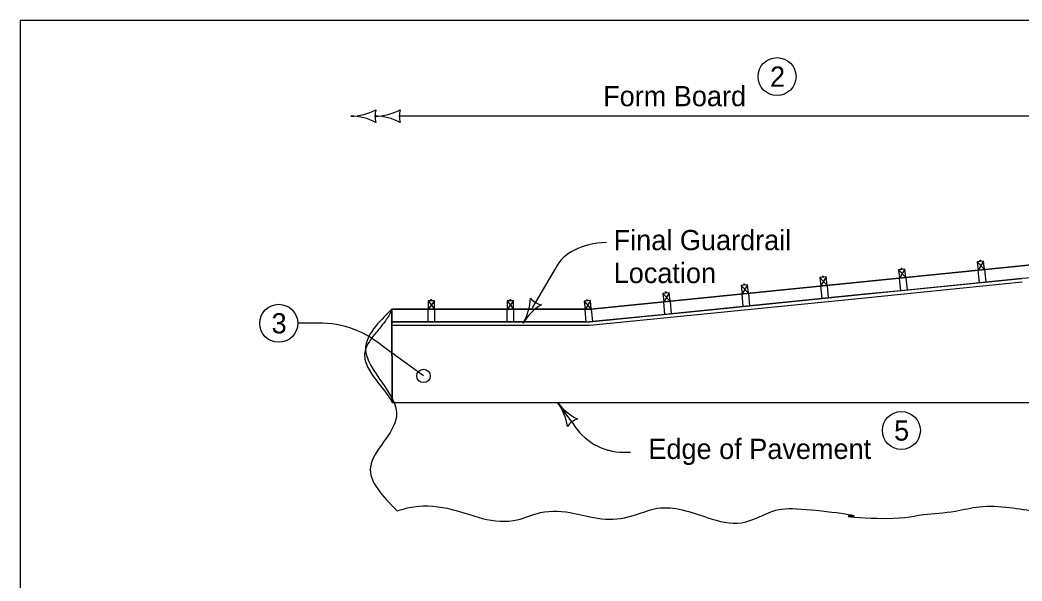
# Model space of a CAD drawing. Extents: x -1548 to 1548, y -960 to 993.
# Drawn here: x -1548 to -756, y 206 to 650 of the extents above; entities that cross this region are included whole.
import ezdxf

# ---------------------------------------------------------------- set-up
doc = ezdxf.new("R2010")
doc.units = 0
for name, color, linetype in [('dsnCellElements', 7, 'Continuous'), ('dsnStdBorder', 7, 'Continuous'), ('dsnStdDimension', 7, 'Continuous'), ('dsnStdLabel', 7, 'Continuous'), ('dsnStdLineWork', 7, 'Continuous'), ('dsnStdNote', 7, 'Continuous'), ('Level 4', 7, 'Continuous')]:
    doc.layers.add(name, color=color, linetype=linetype)

msp = doc.modelspace()

# ---------------------------------------------------------------- linework, layer by layer
at = {"layer": 'dsnCellElements'}
for p, q in [((-786.44, 459.3), (-790.75, 452.16)), ((-789.02, 460.01), (-789.03, 460.08)), ((-853.6, 452.55), (-847.96, 446.41)), ((-848.63, 453.05), (-852.93, 445.91)), ((-851.21, 453.76), (-851.22, 453.83)), ((-791.41, 458.8), (-785.77, 452.66)), ((-790.75, 452.16), (-785.77, 452.66)), ((-789.75, 442.2), (-790.75, 452.16)), ((-785.77, 452.66), (-784.77, 442.71)), ((-915.79, 446.3), (-910.15, 440.16)), ((-910.81, 446.8), (-915.12, 439.66)), ((-913.4, 447.51), (-913.4, 447.58)), ((-880.54, 433.08), (-756.17, 445.58)), ((-852.93, 445.91), (-847.96, 446.41)), ((-851.93, 435.95), (-852.93, 445.91)), ((-847.96, 446.41), (-846.95, 436.46)), ((-727.23, 447.86), (-756.17, 445.58)), ((-977.97, 440.05), (-972.33, 433.91)), ((-973, 440.55), (-977.31, 433.41)), ((-975.58, 441.26), (-975.59, 441.33)), ((-915.12, 439.66), (-910.14, 440.16)), ((-914.12, 429.7), (-915.12, 439.66)), ((-910.14, 440.16), (-909.14, 430.21)), ((-851.93, 435.95), (-880.54, 433.08)), ((-880.27, 430.39), (-755.9, 442.89)), ((-880.27, 430.39), (-755.9, 442.89)), ((-846.95, 436.46), (-851.93, 435.95)), ((-846.95, 436.46), (-851.93, 435.95)), ((-784.77, 442.71), (-789.75, 442.2)), ((-1225.42, 427.94), (-1220.42, 421.27)), ((-1220.42, 427.94), (-1225.42, 421.27)), ((-1222.92, 428.91), (-1222.92, 428.98)), ((-1162.92, 427.94), (-1157.92, 421.27)), ((-1157.92, 427.94), (-1162.92, 421.27)), ((-1160.42, 428.91), (-1160.42, 428.98)), ((-1102.07, 427.58), (-1096.43, 421.44)), ((-1097.09, 428.07), (-1101.41, 420.94)), ((-1099.68, 428.79), (-1099.68, 428.86)), ((-1039.88, 433.79), (-1034.24, 427.66)), ((-1034.9, 434.29), (-1039.22, 427.16)), ((-1039.22, 427.16), (-1034.24, 427.66)), ((-1037.49, 435.01), (-1037.5, 435.08)), ((-1034.24, 427.66), (-1033.24, 417.7)), ((-1004.91, 420.58), (-880.54, 433.08)), ((-1004.64, 417.89), (-880.27, 430.39)), ((-1004.64, 417.89), (-880.27, 430.39)), ((-977.31, 433.41), (-972.33, 433.91)), ((-976.31, 423.45), (-977.31, 433.41)), ((-972.33, 433.91), (-971.33, 423.96)), ((-914.12, 429.7), (-971.33, 423.96)), ((-909.14, 430.21), (-914.12, 429.7)), ((-909.14, 430.21), (-914.12, 429.7)), ((-880.54, 433.08), (-909.14, 430.21)), ((-1225.42, 421.27), (-1220.42, 421.27)), ((-1225.42, 411.26), (-1225.42, 421.27)), ((-1220.42, 421.27), (-1220.42, 411.26)), ((-1162.92, 421.27), (-1157.92, 421.27)), ((-1162.92, 411.26), (-1162.92, 421.27)), ((-1157.92, 421.27), (-1157.92, 411.26)), ((-1101.41, 420.94), (-1096.43, 421.44)), ((-1100.41, 410.98), (-1101.41, 420.94)), ((-1097.76, 411.25), (-1004.91, 420.58)), ((-1096.43, 421.44), (-1095.43, 411.48)), ((-1038.22, 417.2), (-1039.22, 427.16)), ((-1004.91, 420.58), (-1033.24, 417.73)), ((-976.31, 423.45), (-1004.91, 420.58)), ((-971.33, 423.96), (-976.31, 423.45)), ((-971.33, 423.96), (-976.31, 423.45)), ((-1097.49, 408.55), (-1004.64, 417.89)), ((-1097.49, 408.55), (-1004.64, 417.89)), ((-1038.22, 417.23), (-1095.43, 411.48)), ((-1033.24, 417.7), (-1038.22, 417.2)), ((-1033.24, 417.7), (-1038.22, 417.2)), ((-1033.24, 417.73), (-1033.24, 417.7)), ((-1254.17, 411.26), (-1254.17, 408.55)), ((-1254.17, 411.26), (-1129.17, 411.26)), ((-1254.17, 408.55), (-1129.17, 408.55)), ((-1254.17, 408.55), (-1129.17, 408.55)), ((-1220.42, 411.26), (-1225.42, 411.26)), ((-1157.92, 411.26), (-1162.92, 411.26)), ((-1157.92, 411.26), (-1162.92, 411.26)), ((-1129.17, 411.26), (-1157.92, 411.26)), ((-1100.44, 411.26), (-1129.17, 411.26)), ((-1129.17, 411.26), (-1097.63, 411.26)), ((-1129.17, 408.55), (-1097.49, 408.55)), ((-1129.17, 408.55), (-1097.49, 408.55)), ((-1100.41, 410.98), (-1100.44, 411.26)), ((-1095.43, 411.48), (-1100.41, 410.98)), ((-1095.43, 411.48), (-1095.43, 411.48))]:
    msp.add_line(p, q, dxfattribs=at)
for points in [[(-790.75, 452.16), (-785.77, 452.66), (-786.44, 459.3), (-791.41, 458.8)], [(-852.93, 445.91), (-847.96, 446.41), (-848.63, 453.05), (-853.6, 452.55)], [(-915.12, 439.66), (-910.15, 440.16), (-910.81, 446.8), (-915.79, 446.3)], [(-977.31, 433.41), (-972.33, 433.91), (-973, 440.55), (-977.97, 440.05)], [(-1225.42, 421.27), (-1220.42, 421.27), (-1220.42, 427.94), (-1225.42, 427.94)], [(-1162.92, 421.27), (-1157.92, 421.27), (-1157.92, 427.94), (-1162.92, 427.94)], [(-1101.41, 420.94), (-1096.43, 421.44), (-1097.09, 428.07), (-1102.07, 427.58)], [(-1039.22, 427.16), (-1034.24, 427.66), (-1034.9, 434.29), (-1039.88, 433.79)]]:
    msp.add_lwpolyline(points, close=True, dxfattribs=at)
for points in [[(-789.26, 459.01), (-789.3, 459.44), (-788.64, 459.51), (-788.6, 459.08)], [(-789.16, 459.46), (-789.22, 459.99), (-788.83, 460.03), (-788.78, 459.49)], [(-851.45, 452.76), (-851.49, 453.19), (-850.82, 453.26), (-850.78, 452.83)], [(-851.35, 453.21), (-851.4, 453.74), (-851.02, 453.78), (-850.96, 453.24)], [(-913.63, 446.51), (-913.67, 446.94), (-913.01, 447.01), (-912.97, 446.58)], [(-913.54, 446.96), (-913.59, 447.49), (-913.2, 447.53), (-913.15, 446.99)], [(-756.17, 445.58), (-784.77, 442.71), (-789.75, 442.2), (-846.95, 436.46)], [(-975.82, 440.26), (-975.86, 440.69), (-975.2, 440.76), (-975.16, 440.33)], [(-975.72, 440.71), (-975.78, 441.24), (-975.39, 441.28), (-975.34, 440.74)], [(-1223.25, 427.94), (-1223.25, 428.37), (-1222.59, 428.37), (-1222.59, 427.94)], [(-1223.11, 428.37), (-1223.11, 428.91), (-1222.73, 428.91), (-1222.73, 428.37)], [(-1160.75, 427.94), (-1160.75, 428.37), (-1160.09, 428.37), (-1160.09, 427.94)], [(-1160.61, 428.37), (-1160.61, 428.91), (-1160.23, 428.91), (-1160.23, 428.37)], [(-1099.91, 427.79), (-1099.96, 428.22), (-1099.29, 428.29), (-1099.25, 427.86)], [(-1099.82, 428.23), (-1099.87, 428.77), (-1099.48, 428.81), (-1099.43, 428.27)], [(-1037.72, 434.01), (-1037.77, 434.44), (-1037.1, 434.51), (-1037.06, 434.08)], [(-1037.63, 434.45), (-1037.68, 434.99), (-1037.29, 435.03), (-1037.24, 434.49)], [(-1098.92, 421.19), (-1101.41, 420.94), (-1101.41, 420.94)], [(-1038.22, 417.2), (-1038.22, 417.23)], [(-1162.92, 411.26), (-1220.42, 411.26), (-1225.42, 411.26), (-1254.17, 411.26)], [(-1095.43, 411.48), (-1097.63, 411.26), (-1097.76, 411.25), (-1100.41, 410.98)]]:
    msp.add_lwpolyline(points, dxfattribs=at)
at = {"layer": 'dsnStdBorder'}
for q in [(-1547.84, -960), (1547.84, 650)]:
    msp.add_line((-1547.84, 650), q, dxfattribs=at)
at = {"layer": 'dsnStdDimension'}
msp.add_line((-1247.36, 574.13), (-342.58, 574.13), dxfattribs=at)
for centre, radius, start, end in [((-1286.58, 616.47), 42.5, 270, 298.07249), ((-1267.36, 616.47), 42.5, 270, 298.07249), ((-1250.95, 573.97), 16.42, 162.26665, 197.73335), ((-1231.73, 573.97), 16.42, 162.26665, 197.73335), ((-1286.58, 531.47), 42.5, 61.92751, 90), ((-1267.36, 531.47), 42.5, 61.92751, 90)]:
    msp.add_arc(centre, radius, start, end, dxfattribs=at)
at = {"layer": 'dsnStdLabel'}
for p, q in [((-1124.66, 453.64), (-1143.21, 422.3)), ((-1111.04, 331.19), (-1123.15, 347.64)), ((-1070.95, 308.12), (-1065.51, 308.12))]:
    msp.add_line(p, q, dxfattribs=at)
for centre, radius, start, end in [((-1186.97, 431.8), 42.5, 329.37973, 357.45222), ((-1132.24, 440.82), 16.42, 221.64638, 257.11308), ((-1113.82, 388.51), 42.5, 121.30724, 149.37973), ((-1088.93, 372.84), 42.5, 216.37256, 244.44505), ((-1157.37, 322.43), 42.5, 8.30007, 36.37256), ((-1102.02, 318.95), 16.42, 108.63921, 144.10591), ((-1070.9, 354.58), 46.46, 210.22743, 270)]:
    msp.add_arc(centre, radius, start, end, dxfattribs=at)
msp.add_ellipse((-1043.56, 414.6), major_axis=(-81.09, 39.04), ratio=0.555556, start_param=5.482641, end_param=6.283185, dxfattribs=at)
at = {"layer": 'dsnStdLineWork'}
for p, q in [((-1096.43, 421.27), (-732.85, 458.06)), ((-893.02, 443.91), (-893.02, 443.99)), ((-1254.17, 421.27), (-1096.43, 421.27)), ((-1253.65, 347.64), (269.95, 347.64))]:
    msp.add_line(p, q, dxfattribs=at)
msp.add_circle((-1229.05, 368.54), 5.33, dxfattribs=at)
for points in [[(-1254.17, 421.27), (-1274.82, 389.72), (-1250.46, 336.63), (-1270.92, 296.65), (-1249.88, 261.83)], [(-1249.88, 261.83), (-1240.46, 264.41), (-1210.23, 263.83), (-1182.29, 255.85), (-1154.92, 254.71), (-1136.67, 260.41), (-1109.87, 259.84), (-1085.35, 255.28), (-1061.4, 258.7), (-1044.3, 263.83), (-1004.38, 256.42), (-977.58, 252.42), (-953.06, 261.55), (-930.25, 263.26), (-891.48, 257.56), (-892.05, 257.56), (-870.89, 255.96), (-833.83, 258.81), (-808.74, 261.66), (-789.92, 265.08), (-765.97, 264.51), (-744.3, 261.09), (-718.64, 256.53), (-685, 257.67), (-653.63, 263.94), (-628.54, 263.94), (-596.61, 256.53), (-567.53, 253.67), (-533.89, 260.52), (-501.38, 263.94), (-467.17, 257.1), (-441.51, 254.24), (-419.27, 257.67), (-391.33, 273.07), (-381.07, 275.35), (-356.55, 277.63), (-325.88, 278.2), (-304.78, 278.2), (-251.47, 268.92)]]:
    msp.add_spline(points, degree=3, dxfattribs=at)
at = {"layer": 'dsnStdNote'}
for p, q in [((-1316.43, 410.15), (-1328.42, 410.15)), ((-1229.05, 368.54), (-1261.44, 392.02))]:
    msp.add_line(p, q, dxfattribs=at)
for centre in [(-949.67, 605.26), (-1343.42, 410.15), (-851.43, 325.38)]:
    msp.add_circle(centre, 15, dxfattribs=at)
msp.add_arc((-1311.25, 333.38), 76.94, 49.65511, 93.85773, dxfattribs=at)
at = {"layer": 'Level 4'}
for p, q in [((-732.85, 458.06), (-1096.43, 421.27)), ((-1096.43, 421.27), (-1254.17, 421.27)), ((-1254.17, 421.27), (-1253.71, 347.64)), ((-1253.71, 347.64), (-1254.17, 421.27)), ((-1253.71, 347.64), (-351, 347.64))]:
    msp.add_line(p, q, dxfattribs=at)
msp.add_spline([(-1254.17, 421.27), (-1255.97, 417.05), (-1258.42, 413.04), (-1264.41, 405.39), (-1270.44, 397.79), (-1272.94, 393.84), (-1273.97, 391.81), (-1274.42, 390.77), (-1274.63, 390.24), (-1274.72, 389.98), (-1274.82, 389.72), (-1274.66, 379.26), (-1268.97, 368.72), (-1260.93, 358.16), (-1257.02, 352.89), (-1253.71, 347.64)], degree=3, dxfattribs=at)

# ---------------------------------------------------------------- texts
at = {"layer": 'dsnStdDimension'}
msp.add_text('Form Board', height=16, dxfattribs=at).set_placement((-1087.12, 581.82))
at = {"layer": 'dsnStdLabel'}
for s, p in [('Final Guardrail ', (-1078.76, 467.97)), ('Location', (-1078.76, 441.97)), ('Edge of Pavement', (-1051.31, 302.85))]:
    msp.add_text(s, height=16, dxfattribs=at).set_placement(p)
at = {"layer": 'dsnStdNote'}
for s, p in [('2', (-955.21, 597.26)), ('3', (-1349.08, 402.15)), ('5', (-857.15, 317.38))]:
    msp.add_text(s, height=16, dxfattribs=at).set_placement(p)

doc.saveas('drawing.dxf')
